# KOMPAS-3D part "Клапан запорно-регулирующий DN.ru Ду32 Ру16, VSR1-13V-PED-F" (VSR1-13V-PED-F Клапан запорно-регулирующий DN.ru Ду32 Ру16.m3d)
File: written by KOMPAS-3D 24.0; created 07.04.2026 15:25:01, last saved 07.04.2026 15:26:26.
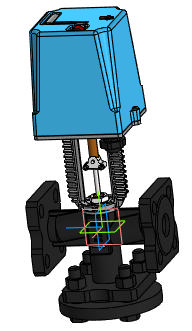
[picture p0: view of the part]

Document properties: Автор: R2D2; Полное имя файла: E:\Работа\Зайцев\Солянка\VSR1-13V-PED-F Клапан запорно-регулирующий DN.ru\DN32\VSR1-13V-PED-F Клапан запорно-регулирующий DN.ru Ду32 Ру16.m3d

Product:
- Part/product: Клапан запорно-регулирующий DN.ru Ду32 Ру16  | designation VSR1-13V-PED-F
    Масса: 9.2
    Раздел спецификации: Прочие изделия
    Примечание: D090-02889

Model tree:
1. Операция без истории:1  (labels: SHAPEOBJECT3D_ATTR_BUTT)

Expressions: VSR1-13V-PED-F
